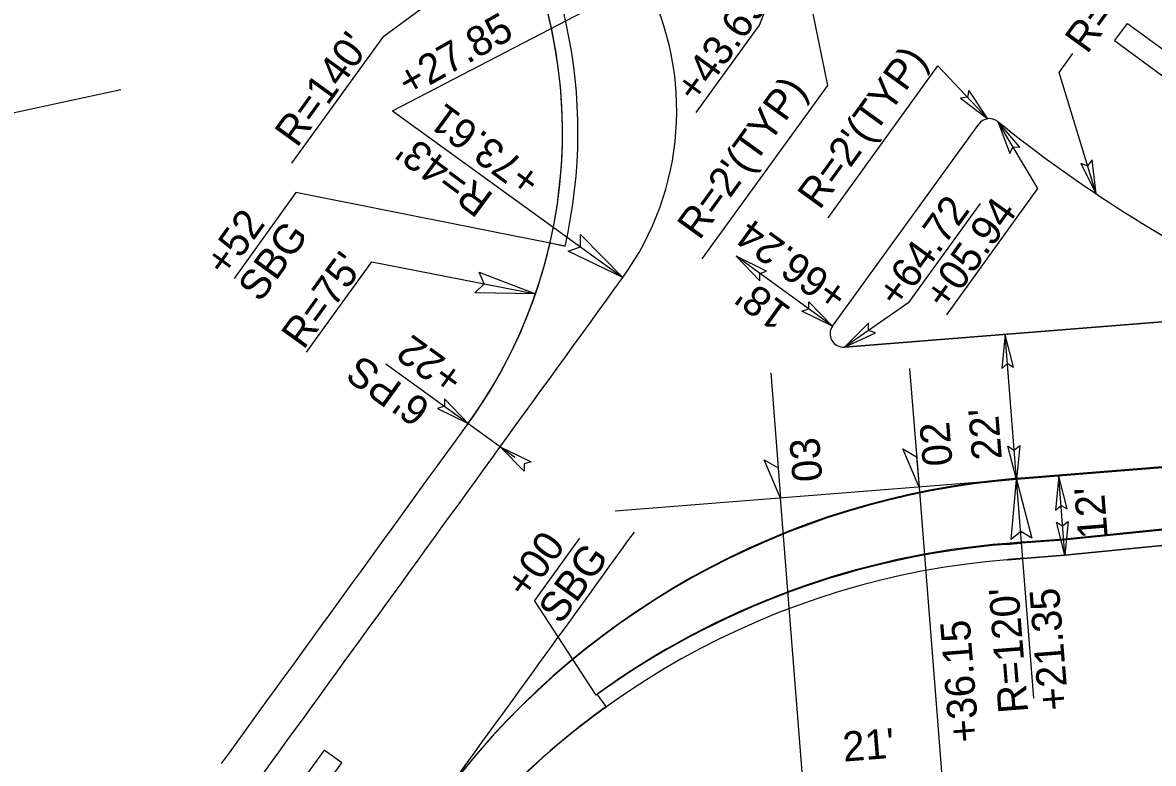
# Model space of a CAD drawing. Extents: x 1183930 to 1185370, y 573068 to 574871.
# Drawn here: x 1184226.2 to 1184397.2, y 573704.9 to 573816.9 of the extents above; entities that cross this region are included whole.
import ezdxf

# ---------------------------------------------------------------- set-up
doc = ezdxf.new("R2010")
doc.units = 0
for name, color, linetype in [('Default', 7, 'Continuous'), ('E_NCDOT_Terrain_Model_Breakline', 7, 'Continuous'), ('E_NCDOT_Terrain_Model_Contour_Minor', 7, 'Continuous'), ('E_NCDOT_Terrain_Model_Points_High', 7, 'Continuous'), ('E_NCDOT_Terrain_Model_Triangles', 7, 'Continuous'), ('E_NCDOT_Vertical_Profile_Ground_Line', 7, 'Continuous'), ('P_NCDOT_Horizontal_Alignment', 7, 'Continuous'), ('P_NCDOT_Horizontal_Alignment_Tick_Large', 7, 'Continuous'), ('PC_BEAM', 7, 'Continuous'), ('PC_COLUMN', 7, 'Continuous'), ('PC_OBJECT', 7, 'Continuous'), ('PC_PADFOOTING', 7, 'Continuous'), ('PC_SLAB', 7, 'Continuous')]:
    doc.layers.add(name, color=color, linetype=linetype)

msp = doc.modelspace()

# ---------------------------------------------------------------- linework, layer by layer
for points in [[(1184338.73, 573779.29), (1184334.12, 573781.55), (1184337.72, 573777.84), (1184337.72, 573778.94)], [(1184345.11, 573774.67), (1184348.7, 573771), (1184344.05, 573773.25), (1184345.1, 573773.6)], [(1184376.06, 573764.78), (1184374.79, 573769.75), (1184374.29, 573764.61), (1184375.14, 573765.32)], [(1184288.98, 573758.54), (1184293.59, 573756.28), (1184289.99, 573759.99), (1184289.99, 573758.88)], [(1184302.04, 573749.09), (1184298.45, 573752.76), (1184303.1, 573750.5), (1184302.05, 573750.16)], [(1184377, 573752.94), (1184376.53, 573747.82), (1184375.23, 573752.83), (1184376.18, 573752.25)], [(1184384.17, 573743.35), (1184382.9, 573748.33), (1184382.4, 573743.18), (1184383.25, 573743.9)], [(1184384.31, 573741.48), (1184383.84, 573736.36), (1184382.55, 573741.37), (1184383.49, 573740.79)]]:
    msp.add_lwpolyline(points, close=True)
at = {"layer": 'Default'}
msp.add_open_spline([(1184374.92, 573738), (1184374.94, 573738), (1184375.01, 573738.01), (1184375.14, 573738.02), (1184375.25, 573738.03), (1184375.37, 573738.04), (1184375.49, 573738.05), (1184375.61, 573738.06), (1184375.73, 573738.08), (1184375.85, 573738.09), (1184375.97, 573738.1), (1184376.09, 573738.11), (1184376.21, 573738.12), (1184376.33, 573738.13), (1184376.45, 573738.14), (1184376.57, 573738.15), (1184376.69, 573738.16), (1184376.81, 573738.17), (1184376.94, 573738.18), (1184377.05, 573738.19), (1184377.19, 573738.2), (1184377.27, 573738.2), (1184377.29, 573738.21)], degree=3, dxfattribs=at)
at = {"layer": 'E_NCDOT_Terrain_Model_Breakline'}
for p, q in [((1184348.7, 573771), (1184370.8, 573801.54)), ((1184350.48, 573767.83), (1184412.9, 573772.77))]:
    msp.add_line(p, q, dxfattribs=at)
for centre, radius, start, end in [((1184372.42, 573800.36), 2, 51.2694, 144.103), ((1184508.19, 573969.64), 215, 231.2694, 243.904), ((1184350.32, 573769.82), 2, 144.103, 274.5263)]:
    msp.add_arc(centre, radius, start, end, dxfattribs=at)
at = {"layer": 'E_NCDOT_Terrain_Model_Contour_Minor'}
for p, q in [((1184280.82, 573814.8), (1184311.8, 573837.62)), ((1184337.65, 573816.49), (1184342.28, 573828.57)), ((1184347.97, 573807.36), (1184343.91, 573827.44)), ((1184282.14, 573803.55), (1184320.31, 573823.35)), ((1184328.09, 573803.28), (1184337.65, 573816.49)), ((1184266.95, 573795.64), (1184280.82, 573814.8)), ((1184382.95, 573809.33), (1184385.01, 573812.18)), ((1184348.01, 573787.38), (1184364.63, 573810.34)), ((1184364.63, 573810.34), (1184372.16, 573802.34)), ((1184388.58, 573790.99), (1184382.95, 573809.33)), ((1184328.99, 573781.15), (1184347.97, 573807.36)), ((1184282.14, 573803.55), (1184316.97, 573778.33)), ((1184379.76, 573791.78), (1184373.68, 573801.92)), ((1184365.96, 573772.71), (1184379.76, 573791.78)), ((1184360.22, 573774.54), (1184371.07, 573789.53)), ((1184269.14, 573767.05), (1184279.05, 573780.73)), ((1184279.05, 573780.73), (1184303.78, 573775.88)), ((1184360.22, 573774.54), (1184350.48, 573767.83)), ((1184379.15, 573714.75), (1184376.53, 573747.82))]:
    msp.add_line(p, q, dxfattribs=at)
for points in [[(1184368.05, 573805.43), (1184372.16, 573802.34), (1184369.32, 573806.67), (1184369.11, 573805.58)], [(1184377.03, 573798.03), (1184373.68, 573801.92), (1184375.52, 573797.1), (1184375.96, 573798.11)], [(1184386.26, 573795.58), (1184388.58, 573790.99), (1184387.94, 573796.12), (1184387.27, 573795.24)], [(1184310.59, 573784.86), (1184316.97, 573778.33), (1184308.7, 573782.34), (1184310.57, 573782.96)], [(1184295.25, 573779.13), (1184303.78, 573775.88), (1184294.59, 573776.05), (1184296.03, 573777.4)], [(1184354.15, 573771.42), (1184350.48, 573767.83), (1184355.18, 573769.98), (1184354.14, 573770.35)], [(1184375.69, 573738.73), (1184376.53, 573747.82), (1184378.84, 573738.93), (1184377.15, 573739.95)]]:
    msp.add_lwpolyline(points, close=True, dxfattribs=at)
at = {"layer": 'E_NCDOT_Terrain_Model_Points_High'}
for p, q in [((1184348.7, 573771), (1184370.8, 573801.54)), ((1184412.9, 573772.77), (1184350.48, 573767.83))]:
    msp.add_line(p, q, dxfattribs=at)
for centre, radius, start, end in [((1184372.42, 573800.36), 2, 51.2694, 144.103), ((1184508.19, 573969.64), 215, 231.2694, 243.904), ((1184350.32, 573769.82), 2, 144.103, 274.5263)]:
    msp.add_arc(centre, radius, start, end, dxfattribs=at)
at = {"layer": 'E_NCDOT_Terrain_Model_Triangles'}
for p, q in [((1184383.64, 573738.69), (1184433.67, 573743.75)), ((1184377.29, 573738.21), (1184383.64, 573738.69))]:
    msp.add_line(p, q, dxfattribs=at)
for centre, radius, start, end in [((1184232.86, 573800.29), 77.33, 347.1573, 37.4184), ((1184384.59, 573616.05), 122.33, 94.5364, 125.8411)]:
    msp.add_arc(centre, radius, start, end, dxfattribs=at)
at = {"layer": 'E_NCDOT_Vertical_Profile_Ground_Line'}
for p, q in [((1184433.58, 573741.4), (1184383.84, 573736.36)), ((1184383.84, 573736.36), (1184433.58, 573741.4)), ((1184383.84, 573736.36), (1184377.47, 573735.88)), ((1184377.47, 573735.88), (1184383.84, 573736.36))]:
    msp.add_line(p, q, dxfattribs=at)
for centre, radius, start, end in [((1184232.86, 573800.29), 75, 324.0683, 37.4184), ((1124762.27, 616900.03), 73521.16, 324.018802, 324.0682713), ((1124762.27, 616900.03), 73521.16, 324.018802, 324.0682713), ((1124762.27, 616900.03), 73521.16, 324.018802, 324.0682713), ((1184384.59, 573616.05), 120, 94.5263, 144.0215)]:
    msp.add_arc(centre, radius, start, end, dxfattribs=at)
for points in [[(1184377.47, 573735.88), (1184377.43, 573735.88), (1184377.35, 573735.87), (1184377.24, 573735.86), (1184377.12, 573735.85), (1184377, 573735.84), (1184376.88, 573735.83), (1184376.77, 573735.82), (1184376.65, 573735.81), (1184376.53, 573735.8), (1184376.41, 573735.79), (1184376.3, 573735.78), (1184376.18, 573735.77), (1184376.06, 573735.76), (1184375.94, 573735.75), (1184375.83, 573735.74), (1184375.71, 573735.73), (1184375.59, 573735.72), (1184375.47, 573735.71), (1184375.36, 573735.7), (1184375.24, 573735.69), (1184375.16, 573735.68), (1184375.12, 573735.67)], [(1184375.12, 573735.67), (1184375.16, 573735.68), (1184375.24, 573735.69), (1184375.36, 573735.7), (1184375.47, 573735.71), (1184375.59, 573735.72), (1184375.71, 573735.73), (1184375.83, 573735.74), (1184375.94, 573735.75), (1184376.06, 573735.76), (1184376.18, 573735.77), (1184376.3, 573735.78), (1184376.41, 573735.79), (1184376.53, 573735.8), (1184376.65, 573735.81), (1184376.77, 573735.82), (1184376.88, 573735.83), (1184377, 573735.84), (1184377.12, 573735.85), (1184377.24, 573735.86), (1184377.35, 573735.87), (1184377.43, 573735.88), (1184377.47, 573735.88)]]:
    msp.add_open_spline(points, degree=3, dxfattribs=at)
at = {"layer": 'P_NCDOT_Horizontal_Alignment'}
for q in [(1184315.83, 573743.02), (1184376.53, 573747.82), (1184376.53, 573747.82)]:
    msp.add_line((1184432.71, 573752.27), q, dxfattribs=at)
for centre, radius, start, end in [((1184282.14, 573803.55), 43, 324.0929, 27.4188), ((1124762.27, 616900.03), 73527.16, 323.9876373, 324.0928744), ((1124762.27, 616900.03), 73527.16, 323.9876373, 324.0928744), ((1184386, 573628.2), 120, 94.5263, 144.0298), ((1184386, 573628.2), 120, 94.5263, 144.0298), ((1124762.27, 616900.03), 73551.16, 323.9876373, 324.0693925)]:
    msp.add_arc(centre, radius, start, end, dxfattribs=at)
at = {"layer": 'P_NCDOT_Horizontal_Alignment_Tick_Large'}
for p, q in [((1184383.84, 573736.36), (1184433.58, 573741.4)), ((1184383.84, 573736.36), (1184433.58, 573741.4)), ((1184377.47, 573735.88), (1184383.84, 573736.36)), ((1184377.47, 573735.88), (1184383.84, 573736.36))]:
    msp.add_line(p, q, dxfattribs=at)
for centre, radius, start, end in [((1184232.86, 573800.29), 75, 324.0683, 57.3255), ((1124762.27, 616900.03), 73521.16, 324.018802, 324.0682713), ((1124762.27, 616900.03), 73521.16, 324.018802, 324.0682713), ((1184384.59, 573616.05), 120, 94.5263, 144.0215), ((1184384.59, 573616.05), 120, 94.5263, 144.0215)]:
    msp.add_arc(centre, radius, start, end, dxfattribs=at)
msp.add_open_spline([(1184375.12, 573735.67), (1184375.14, 573735.68), (1184375.22, 573735.68), (1184375.36, 573735.7), (1184375.47, 573735.71), (1184375.59, 573735.72), (1184375.71, 573735.73), (1184375.83, 573735.74), (1184375.94, 573735.75), (1184376.06, 573735.76), (1184376.18, 573735.77), (1184376.3, 573735.78), (1184376.41, 573735.79), (1184376.53, 573735.8), (1184376.65, 573735.81), (1184376.77, 573735.82), (1184376.88, 573735.83), (1184377, 573735.84), (1184377.12, 573735.85), (1184377.23, 573735.86), (1184377.37, 573735.87), (1184377.45, 573735.88), (1184377.47, 573735.88)], degree=2, dxfattribs=at)
msp.add_open_spline([(1184375.12, 573735.67), (1184375.14, 573735.68), (1184375.22, 573735.68), (1184375.36, 573735.7), (1184375.47, 573735.71), (1184375.59, 573735.72), (1184375.71, 573735.73), (1184375.83, 573735.74), (1184375.94, 573735.75), (1184376.06, 573735.76), (1184376.18, 573735.77), (1184376.3, 573735.78), (1184376.41, 573735.79), (1184376.53, 573735.8), (1184376.65, 573735.81), (1184376.77, 573735.82), (1184376.88, 573735.83), (1184377, 573735.84), (1184377.12, 573735.85), (1184377.23, 573735.86), (1184377.37, 573735.87), (1184377.45, 573735.88), (1184377.47, 573735.88)], degree=2, dxfattribs=at)
at = {"layer": 'PC_BEAM'}
for p, q in [((1184391.35, 573814.1), (1184393.3, 573816.76)), ((1184393.3, 573816.76), (1184404.59, 573808.48)), ((1184402.63, 573805.82), (1184391.35, 573814.1)), ((1184271.81, 573706.91), (1184263.59, 573695.58)), ((1184274.48, 573704.97), (1184271.81, 573706.91)), ((1184266.26, 573693.64), (1184274.48, 573704.97))]:
    msp.add_line(p, q, dxfattribs=at)
at = {"layer": 'PC_COLUMN'}
for points in [[(1184361.78, 573746.63), (1184359.31, 573752.45), (1184361.41, 573751.24)], [(1184340.84, 573744.97), (1184338.38, 573750.8), (1184340.48, 573749.58)]]:
    msp.add_lwpolyline(points, close=True, dxfattribs=at)
at = {"layer": 'PC_OBJECT'}
for p, q in [((1184305.97, 573783.56), (1184308.26, 573783.1)), ((1184432.83, 573752.43), (1184376.64, 573747.98)), ((1184383.75, 573738.85), (1184433.78, 573743.91)), ((1184377.41, 573738.36), (1184383.75, 573738.85)), ((1184314.44, 573713.48), (1184313.08, 573715.38))]:
    msp.add_line(p, q, dxfattribs=at)
for centre, radius, start, end in [((1184232.86, 573800.29), 77.33, 347.1573, 37.4184), ((1184282.14, 573803.55), 43, 324.0929, 27.4188), ((1184232.86, 573800.29), 75, 324.0683, 347.1074), ((1124762.27, 616900.03), 73527.16, 323.9876373, 324.0928744), ((1124762.27, 616900.03), 73521.16, 324.018802, 324.0682713), ((1184386.11, 573628.36), 120, 94.5263, 144.0298), ((1184384.71, 573616.21), 122.33, 94.5364, 125.8411), ((1184384.71, 573616.21), 120, 125.8426, 144.0215)]:
    msp.add_arc(centre, radius, start, end, dxfattribs=at)
msp.add_open_spline([(1184375.03, 573738.16), (1184375.05, 573738.16), (1184375.12, 573738.17), (1184375.25, 573738.18), (1184375.37, 573738.19), (1184375.49, 573738.2), (1184375.61, 573738.21), (1184375.73, 573738.22), (1184375.85, 573738.23), (1184375.97, 573738.24), (1184376.09, 573738.26), (1184376.21, 573738.27), (1184376.33, 573738.28), (1184376.45, 573738.29), (1184376.57, 573738.3), (1184376.69, 573738.31), (1184376.81, 573738.32), (1184376.93, 573738.33), (1184377.05, 573738.34), (1184377.17, 573738.34), (1184377.31, 573738.36), (1184377.39, 573738.36), (1184377.41, 573738.36)], degree=3, dxfattribs=at)
at = {"layer": 'PC_PADFOOTING'}
for p, q in [((1184154.9, 573788.2), (1184241.05, 573806.78)), ((1184267.55, 573791.19), (1184258.2, 573778.2)), ((1184308.26, 573783.1), (1184267.55, 573791.19)), ((1184348.7, 573771), (1184334.12, 573781.55)), ((1184376.53, 573747.82), (1184374.79, 573769.75)), ((1184281.14, 573765.29), (1184300.64, 573751.18)), ((1184383.84, 573736.36), (1184382.9, 573748.33)), ((1184361.78, 573746.63), (1184365.53, 573699.16)), ((1184344.6, 573697.5), (1184340.84, 573744.97)), ((1184310.42, 573738.95), (1184303.62, 573729.51)), ((1184312.96, 573715.22), (1184303.62, 573729.51))]:
    msp.add_line(p, q, dxfattribs=at)
at = {"layer": 'PC_SLAB'}
for p, q in [((1184360.35, 573764.6), (1184361.78, 573746.63)), ((1184339.34, 573763.94), (1184340.84, 573744.97))]:
    msp.add_line(p, q, dxfattribs=at)

# ---------------------------------------------------------------- texts
at = {"layer": 'E_NCDOT_Terrain_Model_Contour_Minor'}
for s, rotation, p in [("R=215'", 54.103, (1184387.19, 573811.99)), ('+43.69', 54.103, (1184328.18, 573804.47)), ('+27.85', 29.5265, (1184284.59, 573805.54)), ("R=140'", 54.103, (1184267.7, 573797.84)), ("R=2'(TYP)", 54.103, (1184346.75, 573788.43)), ("R=2'(TYP)", 54.103, (1184328.56, 573783.85)), ('+73.61', 143.5927, (1184305, 573793.84)), ("R=43'", 143.5927, (1184297.63, 573790.81)), ('+64.72', 54.103, (1184358.71, 573773.51)), ('+05.94', 54.103, (1184365.85, 573773.21)), ("R=75'", 54.103, (1184268.7, 573767.3)), ("R=120'", 94.5263, (1184378.29, 573712.64)), ('+21.35', 94.5263, (1184384.4, 573713.05))]:
    msp.add_text(s, height=4.5, rotation=rotation, dxfattribs=at).set_placement(p)
at = {"layer": 'PC_PADFOOTING'}
for s, rotation, p in [('+52', 54.2438, (1184257.07, 573778.22)), ('SBG', 54.2438, (1184262.15, 573774.43)), ('+66.24', 144.103, (1184351.43, 573776.52)), ("18'", 144.103, (1184342.65, 573773.62)), ('+22', 144.103, (1184293.29, 573763.91)), ('PS', 144.103, (1184283.88, 573762.08)), ("6'", 144.103, (1184288.17, 573759.17)), ("22'", 94.5269, (1184374.31, 573750.93)), ("12'", 94.5269, (1184390.33, 573739.03)), ('+00', 54.2438, (1184302.48, 573729.52)), ('SBG', 54.2438, (1184307.57, 573725.74)), ('+36.15', 94.5263, (1184370.89, 573708.22)), ("21'", 4.5263, (1184350.4, 573705.15))]:
    msp.add_text(s, height=4.5, rotation=rotation, dxfattribs=at).set_placement(p)
at = {"layer": 'PC_SLAB'}
for s, p in [('02', (1184366.86, 573749.99)), ('03', (1184347.18, 573747.62))]:
    msp.add_text(s, height=4.5, rotation=94.5263, dxfattribs=at).set_placement(p)

doc.saveas('drawing.dxf')
